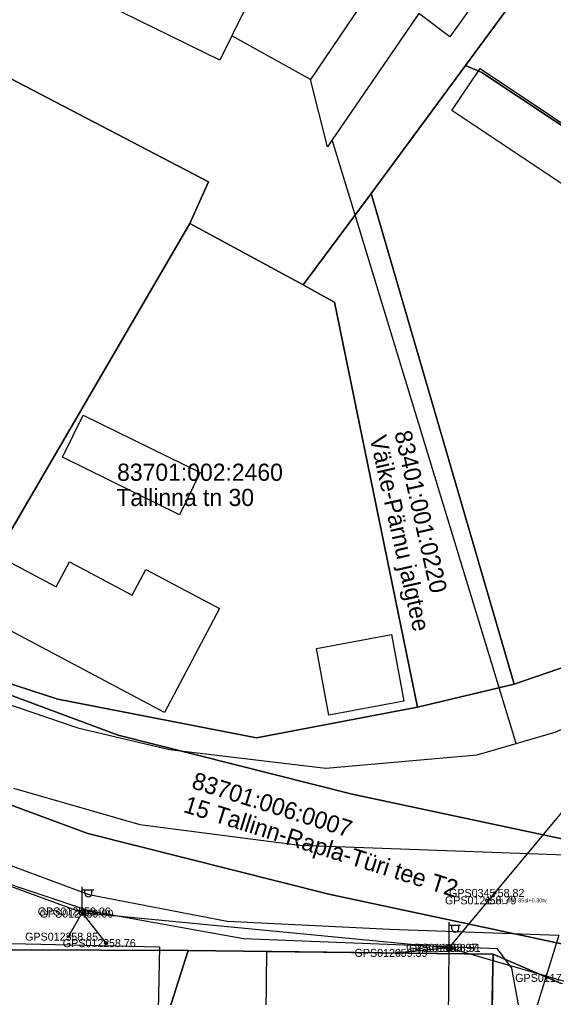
# Model space of a CAD drawing. Extents: x 580119 to 583377, y 6518915 to 6520820.
# Drawn here: x 581821.5 to 581868.2, y 6519742.1 to 6519827.6 of the extents above; entities that cross this region are included whole.
import ezdxf

# ---------------------------------------------------------------- set-up
doc = ezdxf.new("R2010")
doc.units = 0
for name, color, linetype in [('Hoone Elu- või ühiskondlik hoone', 7, 'Continuous'), ('Hoone Kõrval- või tootmishoone', 7, 'Continuous'), ('L_AADRESS', 7, 'Continuous'), ('MAAMUDEL', 7, 'Continuous'), ('MOOTKORG-EH2000', 7, 'Continuous'), ('MOOTMPUNKT', 7, 'Continuous'), ('MOOTNR', 7, 'Continuous'), ('MPOHULIIN', 7, 'Continuous'), ('PIIR', 7, 'Continuous'), ('POST', 7, 'Continuous'), ('Rippe kõrgus', 7, 'Continuous'), ('Tee Kergliiklustee Püsikate', 7, 'Continuous'), ('Tee Liiklusala', 7, 'Continuous'), ('Tee Rada Kivikate', 7, 'Continuous'), ('Tee Tugimaantee Püsikate', 7, 'Continuous'), ('Tee Tänav Püsikate', 7, 'Continuous'), ('TUNNUS', 7, 'Continuous')]:
    doc.layers.add(name, color=color, linetype=linetype)

msp = doc.modelspace()

# ---------------------------------------------------------------- linework, layer by layer
at = {"layer": 'Hoone Elu- või ühiskondlik hoone'}
for points in [[(581856.984, 6519875.286), (581853.098, 6519867.4), (581856.554, 6519865.694), (581855.646, 6519863.855), (581864.258, 6519859.614), (581860.317, 6519851.622), (581854.127, 6519854.679), (581840.077, 6519826.17), (581839.029, 6519824.044), (581826.184, 6519830.377), (581817.036, 6519834.888), (581832.3, 6519865.861), (581840.5, 6519861.812), (581844.117, 6519869.147), (581845.061, 6519868.682), (581850.008, 6519878.72)], [(581820.278, 6519780.362), (581824.714, 6519778.005), (581825.87, 6519780.181), (581831.369, 6519777.267), (581832.569, 6519779.519), (581838.994, 6519776.116), (581834.183, 6519767.017), (581817.805, 6519775.691)], [(581833.758, 6519746.511), (581833.573, 6519738.195), (581819.242, 6519738.513), (581819.434, 6519746.834)], [(581862.914, 6519745.884), (581862.786, 6519735.305), (581843.022, 6519735.524), (581843.135, 6519746.116)]]:
    msp.add_lwpolyline(points, close=True, dxfattribs=at)
at = {"layer": 'Hoone Kõrval- või tootmishoone'}
for points in [[(581874.281, 6519814.988), (581871.826, 6519811.303), (581859.331, 6519819.643), (581861.797, 6519823.331)], [(581837.305, 6519787.987), (581835.503, 6519784.308), (581825.26, 6519789.329), (581827.07, 6519793.016)], [(581855.138, 6519768.013), (581848.576, 6519766.782), (581847.488, 6519772.604), (581854.061, 6519773.827)]]:
    msp.add_lwpolyline(points, close=True, dxfattribs=at)
at = {"layer": 'MOOTMPUNKT'}
for centre in [(581863.072, 6519751.228), (581862.366, 6519750.582), (581826.885, 6519749.609), (581827.113, 6519749.424), (581825.778, 6519747.405), (581829.074, 6519746.841), (581854.592, 6519745.989), (581858.964, 6519746.433), (581859.231, 6519746.419)]:
    msp.add_circle(centre, 0.1, dxfattribs=at)
at = {"layer": 'MPOHULIIN'}
for p, q in [((581826.999, 6519749.516), (581825.778, 6519747.405)), ((581859.098, 6519746.426), (581854.592, 6519745.989)), ((581858.902, 6519725.803), (581859.098, 6519746.426))]:
    msp.add_line(p, q, dxfattribs=at)
for points in [[(581859.098, 6519746.426), (581883.651, 6519775.899), (581910.628, 6519803.454), (581938.377, 6519831.708), (581969.545, 6519863.689), (582004.1, 6519898.634), (582043.971, 6519939.12), (582079.701, 6519981.426), (582116.087, 6520024.187), (582121.9, 6520051.433)], [(581809.431, 6519755.967), (581826.999, 6519749.516), (581859.098, 6519746.426)], [(581859.098, 6519746.426), (581899.654, 6519734.693), (581940.644, 6519722.827), (581965.322, 6519743.428)]]:
    msp.add_lwpolyline(points, dxfattribs=at)
at = {"layer": 'PIIR'}
for points in [[(581566.91, 6519916.24), (581765.76, 6519797.71), (581790.19, 6519783.08), (581813.81, 6519771.08), (581830.15, 6519765.04), (581850.62, 6519759.88), (581900.47, 6519749.25), (581926.68, 6519743.47), (581927.37, 6519746.39), (581972.8, 6519736.39), (581972.1, 6519733.47), (582022.4, 6519721.85)], [(582437.14, 6519631.09), (582279.12, 6519665.47), (582181.52, 6519686.86), (582133.4, 6519697.08), (582083.05, 6519708.05), (582033.29, 6519719.34), (582022.4, 6519721.85), (581972.1, 6519733.47), (581972.8, 6519736.39), (581927.37, 6519746.39), (581926.68, 6519743.47), (581900.47, 6519749.25), (581850.62, 6519759.88), (581830.15, 6519765.04), (581813.81, 6519771.08), (581790.19, 6519783.08), (581765.76, 6519797.71), (581566.91, 6519916.24)], [(582014.36, 6519714.4), (581954.58, 6519728.06), (581945.07, 6519730.21), (581944.37, 6519727.29), (581898.97, 6519737.29), (581899.66, 6519740.22), (581848.58, 6519751.11), (581827.48, 6519756.43), (581810.2, 6519762.82), (581785.83, 6519775.2), (581761.13, 6519789.94), (581562.34, 6519908.5)], [(581720.83, 6519828.38), (581751.53, 6519809.56), (581782.73, 6519790.33), (581814.17, 6519771.63), (581824.87, 6519768.18), (581842.25, 6519764.8), (581856.32, 6519767.48), (581864.77, 6519769.48), (581880.15, 6519774.76), (581904.42, 6519766.33), (581939.76, 6519753.92), (581938.22, 6519748.74), (581987.97, 6519734.16), (582025, 6519727.92), (582043.82, 6519724.92), (582041.99, 6519717.52), (582191.36, 6519685.62), (582375.21, 6519645.73)]]:
    msp.add_lwpolyline(points, dxfattribs=at)
for points in [[(581826.46, 6519873.97), (581841.71, 6519865.75), (581842.83, 6519865.16), (581844.72, 6519868.84), (581853.18, 6519885.33), (581870.06, 6519876.59), (581888.65, 6519861.81), (581876.19, 6519844.87), (581860.51, 6519823.58), (581852.28, 6519812.4), (581846.31, 6519804.4), (581836.4, 6519809.77), (581838.04, 6519813.4), (581804.59, 6519830.86), (581802.65, 6519831.88)], [(581878.19, 6519814.14), (581875.63, 6519816.01), (581874.6, 6519814.57), (581861.96, 6519822.96), (581860.51, 6519823.58), (581876.19, 6519844.87), (581895.07, 6519832.71), (581897.43, 6519832.37), (581900.94, 6519829.02), (581920.78, 6519816.29), (581901.19, 6519796.81), (581877.65, 6519813.18)], [(581804.59, 6519830.86), (581838.04, 6519813.4), (581836.4, 6519809.77), (581814.17, 6519771.63), (581782.73, 6519790.33)], [(581860.51, 6519823.58), (581861.96, 6519822.96), (581874.6, 6519814.57), (581872.5, 6519811.64), (581875.21, 6519809.84), (581877.65, 6519813.18), (581901.19, 6519796.81), (581880.15, 6519774.76), (581864.77, 6519769.48), (581852.28, 6519812.4)], [(581864.77, 6519769.48), (581856.32, 6519767.48), (581849.05, 6519802.9), (581848.05, 6519803.45), (581846.31, 6519804.4), (581852.28, 6519812.4)], [(581836.4, 6519809.77), (581846.31, 6519804.4), (581848.05, 6519803.45), (581849.05, 6519802.9), (581856.32, 6519767.48), (581842.25, 6519764.8), (581824.87, 6519768.18), (581814.17, 6519771.63)], [(581756.15, 6519781.82), (581761.13, 6519789.94), (581785.83, 6519775.2), (581810.2, 6519762.82), (581827.48, 6519756.43), (581848.58, 6519751.11), (581899.66, 6519740.22), (581898.97, 6519737.29), (581944.37, 6519727.29), (581945.07, 6519730.21), (581954.58, 6519728.06), (581950.45, 6519719.52), (581940.85, 6519717.73), (581876.19, 6519740.16), (581862.95, 6519745.89), (581836.27, 6519746.21), (581821.06, 6519746.26), (581818.91, 6519746.03), (581818.63, 6519745.83), (581797.39, 6519753.15), (581799.19, 6519762.22), (581792.48, 6519765.15), (581788.51, 6519764.43)], [(581862.7, 6519735.58), (581862.95, 6519745.89), (581876.19, 6519740.16), (581863.74, 6519715.07), (581855.33, 6519690.59), (581838.33, 6519642.8), (581821.94, 6519597.83), (581818.32, 6519573.11), (581803.96, 6519517.1), (581795.63, 6519521.82), (581799.07, 6519533.63), (581809.3, 6519578.74), (581818.49, 6519614.04), (581825.04, 6519632.45), (581822.37, 6519633.64), (581830.85, 6519658.81), (581839.33, 6519683.07), (581850.1, 6519715.45), (581851.38, 6519719.23), (581853.38, 6519718.73)], [(581818.63, 6519745.83), (581818.91, 6519746.03), (581821.06, 6519746.26), (581836.27, 6519746.21), (581828.64, 6519722.33), (581823.87, 6519707.4), (581799.14, 6519713.16)], [(581836.27, 6519746.21), (581862.95, 6519745.89), (581862.7, 6519735.58), (581853.38, 6519718.73), (581851.38, 6519719.23), (581850.1, 6519715.45), (581828.64, 6519722.33)]]:
    msp.add_lwpolyline(points, close=True, dxfattribs=at)
at = {"layer": 'POST'}
for p, q in [((581826.999, 6519749.766), (581826.999, 6519751.766)), ((581826.999, 6519751.516), (581827.999, 6519751.516)), ((581827.226, 6519751.195), (581827.226, 6519751.516)), ((581827.839, 6519751.195), (581827.839, 6519751.516)), ((581826.999, 6519749.516), (581826.999, 6519749.516)), ((581859.098, 6519746.676), (581859.098, 6519748.676)), ((581859.098, 6519748.426), (581860.098, 6519748.426)), ((581859.324, 6519748.105), (581859.324, 6519748.426)), ((581859.937, 6519748.105), (581859.937, 6519748.426)), ((581859.098, 6519746.426), (581859.098, 6519746.426))]:
    msp.add_line(p, q, dxfattribs=at)
msp.add_lwpolyline([(581829.074, 6519746.841), (581826.999, 6519749.516)], dxfattribs=at)
for centre, radius in [((581826.999, 6519749.516), 0.25), ((581829.074, 6519746.841), 0.125), ((581829.074, 6519746.841), 0.105), ((581829.074, 6519746.841), 0.0851), ((581829.074, 6519746.841), 0.0651), ((581829.074, 6519746.841), 0.0451), ((581829.074, 6519746.841), 0.0251), ((581829.074, 6519746.841), 0.00511), ((581859.098, 6519746.426), 0.25)]:
    msp.add_circle(centre, radius, dxfattribs=at)
for centre in [(581827.532, 6519751.195), (581859.631, 6519748.105)]:
    msp.add_arc(centre, 0.306, 180, 0, dxfattribs=at)
at = {"layer": 'Tee Kergliiklustee Püsikate'}
msp.add_lwpolyline([(581814.375, 6519755.992), (581827.574, 6519751.091), (581839.672, 6519748.76), (581853.903, 6519748.075), (581868.696, 6519747.532)], dxfattribs=at)
at = {"layer": 'Tee Liiklusala'}
for points in [[(581883.12, 6519859.54), (581859.165, 6519826.103), (581856.452, 6519828.136), (581848.866, 6519817.074), (581848.448, 6519816.464), (581846.949, 6519822.369), (581840.077, 6519826.17), (581839.029, 6519824.044), (581826.184, 6519830.377)], [(581720.385, 6519828.523), (581720.945, 6519826.955), (581768.718, 6519797.301), (581810.207, 6519772.249), (581818.526, 6519768.42), (581826.605, 6519765.656), (581834.638, 6519763.763), (581840.218, 6519763.089), (581848.295, 6519762.14), (581861.54, 6519763.296), (581864.958, 6519764.297), (581868.466, 6519765.325), (581882.933, 6519772.243), (581880.53, 6519775.58), (581877.628, 6519779.573), (581889.267, 6519791.94), (581896.552, 6519800.55), (581903.842, 6519794.858), (581906.334, 6519797.606), (581931.916, 6519825.128), (581939.519, 6519834.182)], [(581813.136, 6519581.734), (581814.609, 6519596.327), (581820.112, 6519615.445), (581823.934, 6519625.234), (581847.476, 6519692.072), (581860.775, 6519729.697), (581865.294, 6519740.669), (581864.575, 6519744.639), (581863.32, 6519746.334), (581841.102, 6519747.218), (581827.648, 6519749.647), (581814.586, 6519754.011), (581808.571, 6519747.528), (581803.693, 6519744.783), (581798.267, 6519743.483), (581714.065, 6519731.241), (581710.969, 6519730.467)]]:
    msp.add_lwpolyline(points, dxfattribs=at)
at = {"layer": 'Tee Rada Kivikate'}
msp.add_lwpolyline([(581864.958, 6519764.297), (581850.834, 6519810.62), (581848.866, 6519817.074)], dxfattribs=at)
at = {"layer": 'Tee Tugimaantee Püsikate'}
msp.add_lwpolyline([(581820.976, 6519760.398), (581832.025, 6519757.223), (581846.004, 6519755.411), (581866.884, 6519754.639), (581870.855, 6519754.492)], dxfattribs=at)
at = {"layer": 'Tee Tänav Püsikate'}
for points in [[(581880.88, 6519871.132), (581876.111, 6519865.435), (581846.949, 6519822.369)], [(581868.696, 6519747.532), (581862.937, 6519728.965), (581847.63, 6519684.731), (581827.451, 6519626.917), (581822.865, 6519614.069), (581816.904, 6519592.657), (581815.572, 6519581.172)]]:
    msp.add_lwpolyline(points, dxfattribs=at)

# ---------------------------------------------------------------- texts
at = {"layer": 'L_AADRESS'}
for s, rotation, p in [('Väike-Pärnu jalgtee', 282.70109, (581852.128, 6519791.059)), ('15 Tallinn-Rapla-Türi tee T2', 342.522, (581835.755, 6519758.325))]:
    msp.add_text(s, height=1.5, rotation=rotation, dxfattribs=at).set_placement(p)
msp.add_text('Tallinna tn 30', height=1.5, dxfattribs=at).set_placement((581829.982, 6519785.063))
at = {"layer": 'MAAMUDEL'}
for s, p in [(' kaabel', (581826.885, 6519749.434)), (' kaabel', (581827.113, 6519749.249)), (' tv', (581825.778, 6519747.23)), (' tv', (581854.592, 6519745.814))]:
    msp.add_text(s, height=0.35, dxfattribs=at).set_placement(p)
at = {"layer": 'MOOTKORG-EH2000'}
for s, p in [(' 58.79', (581862.366, 6519750.232)), (' 58.82', (581863.072, 6519750.878)), (' 59.06', (581826.885, 6519749.259)), (' 59.00', (581827.113, 6519749.074)), (' 58.85', (581825.778, 6519747.055)), (' 58.76', (581829.074, 6519746.491)), (' 58.97', (581858.964, 6519746.083)), (' 58.91', (581859.231, 6519746.069)), (' 59.39', (581854.592, 6519745.639))]:
    msp.add_text(s, height=0.7, dxfattribs=at).set_placement(p)
at = {"layer": 'MOOTNR'}
for s, p in [('GPS0121 ', (581858.726, 6519750.232)), ('GPS0345 ', (581859.083, 6519750.878)), ('GPS0125 ', (581823.106, 6519749.259)), ('GPS0124 ', (581823.264, 6519749.074)), ('GPS0123 ', (581821.999, 6519747.055)), ('GPS0122 ', (581825.295, 6519746.491)), ('GPS0119 ', (581855.324, 6519746.083)), ('GPS0118 ', (581855.592, 6519746.069)), ('GPS0120 ', (581850.812, 6519745.639)), ('GPS0117 ', (581864.872, 6519743.455))]:
    msp.add_text(s, height=0.7, dxfattribs=at).set_placement(p)
at = {"layer": 'Rippe kõrgus'}
msp.add_text(' el_mp_ohl7.85si+0.30tv', height=0.35, dxfattribs=at).set_placement((581862.366, 6519750.407))
at = {"layer": 'TUNNUS'}
for s, rotation, p in [('83401:001:0220', 282.70109, (581854.293, 6519791.482)), ('83701:006:0007', 342.522, (581836.477, 6519760.409))]:
    msp.add_text(s, height=1.5, rotation=rotation, dxfattribs=at).set_placement(p)
msp.add_text('83701:002:2460', height=1.5, dxfattribs=at).set_placement((581830.045, 6519787.268))

doc.saveas('drawing.dxf')
